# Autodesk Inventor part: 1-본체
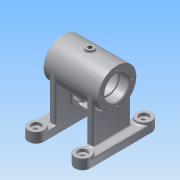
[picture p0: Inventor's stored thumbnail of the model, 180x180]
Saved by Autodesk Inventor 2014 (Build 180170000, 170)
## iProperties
Created: 2015-11
Part Number: 1-본체
Material: 알루미늄 6061
Document SubType Name: Modeling
Designer: 103-06
Density: 2.71 g/cm^3
Appearance: 알루미늄 - 평지
Mass: 357.496 g
Surface Area: 463.75 cm^2
Volume: 131.917 cm^3
Author: 103-06
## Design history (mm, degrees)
sketch "스케치1"
  geometry: C1 r 25 at (0, 0); 1 further point
  constraints: 1 centre point, 1 coincident
  dimensions: "d0" = 50 diameter of C1
extrude "돌출1" new body sketch "스케치1" stored distance "d1" = 70; taper "d2" = 0 deg
sketch "스케치2"
  geometry: C1 r 21 at (0, 0); 1 further point
  constraints: 1 centre point, 1 coincident
  dimensions: "d3" = 42 diameter of C1
extrude "돌출2" cut sketch "스케치2" stored distance "d4" = 42; taper "d5" = 0 deg
node "작업 평면1"
sketch "스케치3"
  geometry: C1 r 5 at (0, 0); 1 further point
  constraints: 1 centre point, 1 coincident
  dimensions: "d7" = 10 diameter of C1
extrude "돌출3" join sketch "스케치3" stored distance "d8" = 42; taper "d9" = 0 deg
node "작업 평면2"
sketch "스케치4"
  geometry: L1 (-28, -25)-(-20, -25); L2 (-20, -25)-(-20, 25); L3 (-20, 25)-(-28, 25); L4 (-28, 25)-(-28, -25); L5 (20, -25)-(28, -25); L6 (28, -25)-(28, 25); L7 (28, 25)-(20, 25); L8 (20, 25)-(20, -25); L9 (0, -4)-(0, 4); L10 (20, -25)-(20, -40); L11 (40, -40)-(40, 40); L12 (20, 40)-(20, 25); L13 (-20, -25)-(-20, -40); L14 (-40, -40)-(-40, 40); L15 (-20, 40)-(-20, 25); A1 r 10 centre (30, -40) between (20, -40) and (40, -40); A2 r 10 centre (30, 40) between (40, 40) and (20, 40); A3 r 10 centre (-30, -40) between (-40, -40) and (-20, -40); A4 r 10 centre (-30, 40) between (-20, 40) and (-40, 40); 2 further points
  constraints: 30 end point, 8 point on circle, 7 parallel, 6 symmetric about line, 4 centre point, 3 tangent, 2 horizontal, 2 perpendicular, 1 coincident, 1 midpoint, 2 other
  dimensions: "d14" = 8 distance of L5.start L5.end; "d15" = 8 distance of L1.start L1.end; "d21" = 50 distance of L5.end L6.end; "d22" = 25 distance from line of L5 point (0, 0); "d23" = 25 distance from line of point (0, 0) L1; "d24" = 20 distance from line of L8 point (0, 0); "d25" = 20 distance from line of L2 point (0, 0); "d28" = 20 diameter of A1; "d29" = 20 diameter of A2; "d30" = 40 vertical distance of A1.centre point (0, 0); "d31" = 80 distance of A2.centre A1.centre; "d32" = 30 horizontal distance of point (0, 0) A1.centre; "d33" = 30 horizontal distance of A2.centre point (0, 0)
extrude "돌출4" join sketch "스케치4" stored distance "d26" = 42; taper "d27" = 0 deg
extrude "돌출5" join sketch "스케치4" distance "d35" = 10; taper "d36" = 0 deg
sketch "스케치5"
  geometry: C1 r 10 at (-40, 30); C2 r 10 at (40, 30); C3 r 10 at (-40, -30); C4 r 10 at (40, -30); A1 r 10 centre (40, 30) between (40, 20) and (40, 40) reference; A2 r 10 centre (-40, 30) between (-40, 40) and (-40, 20) reference; A3 r 10 centre (-40, -30) between (-40, -20) and (-40, -40) reference; A4 r 10 centre (40, -30) between (40, -40) and (40, -20) reference; 1 further point
  constraints: 4 centre point, 4 coincident
  dimensions: "d37" = 20 diameter of C1; "d38" = 20 diameter of C2; "d39" = 20 diameter of C3; "d40" = 20 diameter of C4
extrude "돌출6" join sketch "스케치5" distance "d41" = 3; taper "d42" = 0 deg
hole "구멍1" diameter "d45" = 6; stored, may be unused: countersink angle "d49" = 90 deg, drill point angle "d51" = 118 deg; dims "d43" = 10, "d44" = 10, "d46" = 6, "d47" = 12, "d48" = 4, "d50" = 8
hole "구멍2" diameter "d54" = 6; stored, may be unused: countersink angle "d58" = 90 deg, drill point angle "d60" = 118 deg; dims "d52" = 10, "d53" = 10, "d55" = 6, "d56" = 12, "d57" = 4, "d59" = 8
hole "구멍3" diameter "d63" = 6; stored, may be unused: countersink angle "d67" = 90 deg, drill point angle "d69" = 118 deg; dims "d61" = 10, "d62" = 10, "d64" = 6, "d65" = 12, "d66" = 4, "d68" = 8
hole "구멍4" diameter "d72" = 6; stored, may be unused: countersink angle "d76" = 90 deg, drill point angle "d78" = 118 deg; dims "d70" = 10, "d71" = 10, "d73" = 6, "d74" = 12, "d75" = 4, "d77" = 8
sketch "스케치6"
  geometry: L1 (-58, 20)-(0, 20) reference; L2 (-25, -35)-(-25, 35) reference; L3 (-58, -20)-(0, -20) reference; L4 (-45, 20)-(-45, -20); 1 further point
  constraints: 2 end point, 2 point on line, 1 perpendicular
  dimensions: "d79" = 20 distance between parallel lines of L4 L2
feature "리브1" sketch "스케치6" dims "d80" = 1, "d81" = 8, "d82" = 0, "d83" = 0, "d84" = 1, "d85" = 1
sketch "스케치7"
  geometry: L1 (20.322, 0)-(0, 0) reference; L2 (20.322, 40)-(20.322, 0) reference; L3 (10.161, 31.5)-(10.161, 8.5); L4 (6.661, 28)-(6.661, 12); L5 (13.661, 12)-(13.661, 28); A1 r 3.5 centre (10.161, 28) between (13.661, 28) and (6.661, 28); A2 r 3.5 centre (10.161, 12) between (6.661, 12) and (13.661, 12); 4 further points
  constraints: 8 end point, 6 point on circle, 4 tangent, 3 midpoint, 2 centre point, 2 parallel, 2 point on line, 1 horizontal alignment, 1 vertical alignment
  dimensions: "d86" = 23 distance of L3.start L3.end; "d87" = 7 diameter of A2
extrude "돌출7" cut sketch "스케치7" stored distance "d88" = 3; taper "d89" = 0 deg
hole "구멍5" diameter "d92" = 28; stored, may be unused: countersink angle "d96" = 90 deg, drill point angle "d98" = 118 deg; dims "d90" = 10, "d91" = 10, "d93" = 6, "d94" = 32, "d95" = 12, "d97" = 8
hole "구멍6" diameter "d101" = 28; stored, may be unused: countersink angle "d105" = 90 deg, drill point angle "d107" = 118 deg; dims "d99" = 10, "d100" = 10, "d102" = 6, "d103" = 32, "d104" = 12, "d106" = 8
hole "구멍7" diameter "d110" = 5.188; stored, may be unused: countersink angle "d114" = 90 deg, drill point angle "d116" = 118 deg; dims "d111" = 6, "d112" = 32, "d113" = 12, "d115" = 30, "d144" = 10, "d145" = 10
sketch "스케치8"
  geometry: C1 r 16 at (0, 0) reference; 1 further point
  constraints: 1 horizontal alignment
  dimensions: "d119" = 20 distance of C1.centre point (20, 0)
hole "구멍8" sketch "스케치8" at (20, 0) diameter "d120" = 3.242; stored, may be unused: countersink angle "d124" = 90 deg, drill point angle "d126" = 118 deg; dims "d121" = 8, "d122" = 32, "d123" = 12, "d125" = 10
node "작업 평면4"
  node "작업 평면3"
sketch "스케치9"
  geometry: C1 r 6 at (0, 0); 1 further point
  constraints: 1 centre point, 1 coincident
  dimensions: "d132" = 12 diameter of C1
extrude "돌출8" join sketch "스케치9" stored distance "d133" = 3; taper "d134" = 0 deg
hole "구멍9" diameter "d137" = 5.188; stored, may be unused: countersink angle "d141" = 90 deg, drill point angle "d143" = 118 deg; dims "d135" = 10, "d136" = 10, "d138" = 8, "d139" = 32, "d140" = 12, "d142" = 20
fillet "모깎기1" dims "d146" = 0.3
chamfer "모따기1" distance "d147" = 1; stored, may be unused: second distance "d148" = 2, angle "d149" = 45 deg
fillet "모깎기2" dims "d150" = 2
fillet "모깎기3" dims "d151" = 2
node "작업 평면5"
sketch "스케치10"
  geometry: L1 (-25, -35)-(-25, 35) reference; L2 (-25, -35)-(25, -35) reference; 2 further points
  constraints: 1 coincident, 1 other
feature "엠보싱1" sketch "스케치10" dims "d14" = 8, "d15" = 8, "d21" = 50, "d22" = 25, "d23" = 25, "d24" = 20, "d25" = 20, "d28" = 20, "d29" = 20, "d30" = 40, "d31" = 80, "d32" = 30, "d33" = 30, "d153" = 0.5, "d154" = 0
node "솔리드1"
pattern_circular "원형 패턴1" dims angle "d128" = 360 deg
mirror "대칭1"
other parameters: "d6" = 28, "d10" = -68, "d130" = 120 deg, "d131" = -28, "d152" = -33
